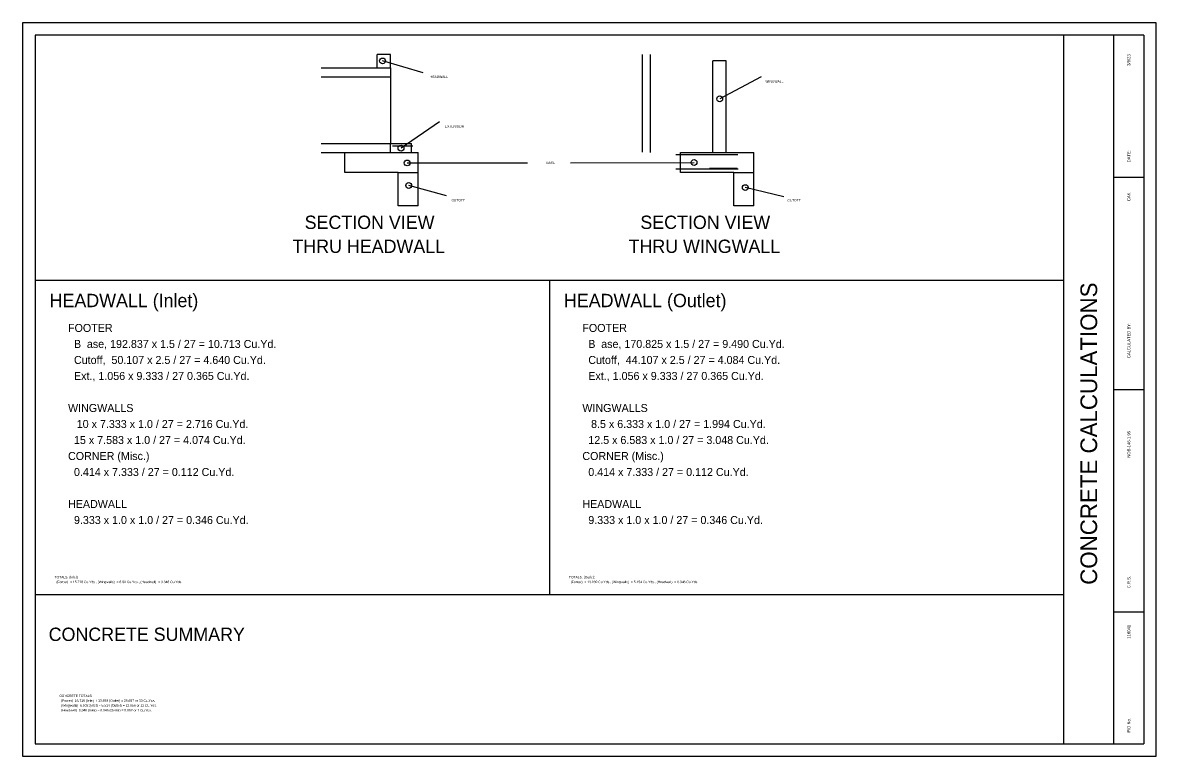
# Model space of a CAD drawing. Extents: x -1609 to 1184, y -412 to 394.
# Drawn here: x 1044.59 to 1078.59, y 161.83 to 183.83 of the extents above; entities that cross this region are included whole.
import ezdxf

# ---------------------------------------------------------------- set-up
doc = ezdxf.new("R2010")
doc.units = 0
for name, color, linetype in [('BD_P_Building', 7, 'Continuous'), ('DR_P_Headwall', 7, 'Continuous'), ('SH_Data', 7, 'Continuous'), ('ST_Details', 7, 'Continuous'), ('ST_Text', 7, 'Continuous')]:
    doc.layers.add(name, color=color, linetype=linetype)

msp = doc.modelspace()

# ---------------------------------------------------------------- linework, layer by layer
at = {"layer": 'DR_P_Headwall'}
for p, q in [((1055.22, 182.475), (1055.22, 182.875)), ((1055.62, 182.875), (1055.22, 182.875)), ((1055.62, 182.475), (1055.62, 182.875)), ((1065.688, 182.685), (1065.288, 182.685)), ((1065.288, 179.941), (1065.288, 182.685)), ((1065.688, 179.941), (1065.688, 182.685)), ((1055.62, 180.208), (1056.253, 180.208)), ((1055.62, 179.941), (1055.62, 180.208)), ((1056.253, 179.941), (1056.253, 180.208)), ((1054.253, 179.941), (1055.62, 179.941)), ((1054.253, 179.341), (1054.253, 179.941)), ((1056.253, 179.941), (1056.453, 179.941)), ((1056.453, 178.341), (1056.453, 179.941)), ((1064.321, 179.941), (1065.288, 179.941)), ((1064.321, 179.341), (1064.321, 179.941)), ((1065.688, 179.941), (1066.521, 179.941)), ((1066.521, 178.341), (1066.521, 179.941)), ((1055.853, 179.341), (1054.253, 179.341)), ((1055.853, 178.341), (1055.853, 179.341)), ((1065.921, 179.341), (1064.321, 179.341)), ((1065.921, 178.341), (1065.921, 179.341)), ((1056.453, 178.341), (1055.853, 178.341)), ((1066.521, 178.341), (1065.921, 178.341))]:
    msp.add_line(p, q, dxfattribs=at)
at = {"layer": 'SH_Data'}
for p, q in [((1056.599, 182.332), (1055.385, 182.686)), ((1066.74, 182.209), (1065.496, 181.548)), ((1057.09, 180.856), (1055.938, 180.072)), ((1056.122, 179.626), (1059.733, 179.633)), ((1061.024, 179.635), (1064.727, 179.642)), ((1057.305, 178.642), (1056.168, 178.95)), ((1067.416, 178.611), (1066.264, 178.888))]:
    msp.add_line(p, q, dxfattribs=at)
for centre in [(1055.385, 182.686), (1065.496, 181.548), (1055.938, 180.072), (1056.122, 179.626), (1064.727, 179.642), (1056.168, 178.95), (1066.264, 178.888)]:
    msp.add_circle(centre, 0.087, dxfattribs=at)
at = {"layer": 'ST_Details'}
for p, q in [((1044.591, 183.833), (1044.591, 161.833)), ((1078.591, 183.833), (1044.591, 183.833)), ((1078.591, 161.833), (1078.591, 183.833)), ((1044.966, 183.458), (1044.966, 162.208)), ((1078.216, 183.458), (1044.966, 183.458)), ((1075.816, 162.208), (1075.816, 183.458)), ((1077.316, 162.208), (1077.316, 183.458)), ((1078.216, 183.458), (1078.216, 162.208)), ((1063.176, 179.95), (1063.176, 182.875)), ((1063.421, 179.941), (1063.421, 182.875)), ((1053.547, 182.475), (1055.62, 182.475)), ((1055.62, 182.475), (1055.62, 182.473)), ((1055.62, 182.475), (1055.62, 182.208)), ((1053.547, 182.208), (1055.62, 182.208)), ((1055.62, 182.208), (1055.62, 180.208)), ((1053.547, 180.208), (1055.62, 180.208)), ((1055.62, 179.941), (1055.62, 180.208)), ((1053.547, 179.941), (1055.62, 179.941)), ((1055.62, 179.941), (1056.453, 179.941)), ((1055.687, 180.141), (1056.294, 180.141)), ((1066.043, 179.87), (1064.177, 179.87)), ((1065.288, 179.941), (1065.688, 179.941)), ((1055.853, 179.341), (1056.453, 179.341)), ((1066.049, 179.44), (1064.182, 179.44)), ((1065.187, 179.475), (1066.021, 179.475)), ((1065.921, 179.341), (1066.521, 179.341)), ((1077.316, 179.205), (1078.216, 179.205)), ((1044.966, 176.113), (1075.816, 176.113)), ((1060.391, 176.113), (1060.391, 166.681)), ((1077.316, 172.833), (1078.216, 172.833)), ((1044.966, 166.681), (1075.816, 166.681)), ((1077.316, 166.166), (1078.216, 166.166)), ((1044.966, 162.208), (1078.216, 162.208)), ((1044.591, 161.833), (1078.591, 161.833))]:
    msp.add_line(p, q, dxfattribs=at)
msp.add_lwpolyline([(1066.021, 179.87), (1065.221, 179.87)], dxfattribs=at)

# ---------------------------------------------------------------- texts
at = {"layer": 'BD_P_Building'}
for s, p in [('HEADWALL', (1056.805, 182.175)), ('WINGWALL', (1066.866, 182.036)), ('EXTENSION', (1057.254, 180.687)), ('BASE', (1060.297, 179.598)), ('CUTOFF', (1057.455, 178.473)), ('CUTOFF', (1067.523, 178.473)), ('TOTALS, (Inlet)', (1045.549, 167.17)), ('  (Footer)  = 15.718 Cu.Yds., (Wingwalls)  = 6.90 Cu.Yds., (Headwall)  = 0.346 Cu.Yds.', (1045.549, 167.026)), ('TOTALS, (Outlet)', (1060.974, 167.17)), ('  (Footer)  = 13.939 Cu.Yds., (Wingwalls)  = 5.154 Cu.Yds., (Headwall)  = 0.346 Cu.Yds.', (1060.974, 167.026)), ('CONCRETE TOTALS', (1045.689, 163.611)), ('  (Footer)  15.718 (Inlet) + 13.939 (Outlet) = 29.657 or 30 Cu.Yds.', (1045.689, 163.467)), ('  (Wingwalls)  6.902 (Inlet) + 5.514 (Outlet) = 12.056 or 12 Cu.Yds.', (1045.689, 163.323)), ('  (Headwall)  0.346 (Inlet) + 0.346 (Outlet) = 0.692 or 1 Cu.Yds.', (1045.689, 163.179))]:
    msp.add_text(s, height=0.072, dxfattribs=at).set_placement(p)
at = {"layer": 'SH_Data'}
for s, p in [('FOOTER', (1045.952, 174.559)), ('FOOTER', (1061.377, 174.559)), ('  B', (1045.952, 174.079)), ('ase, 192.837 x 1.5 / 27 = 10.713 Cu.Yd.', (1046.517, 174.079)), ('  B', (1061.377, 174.079)), ('ase, 170.825 x 1.5 / 27 = 9.490 Cu.Yd.', (1061.942, 174.079)), ('  Cutoff,  50.107 x 2.5 / 27 = 4.640 Cu.Yd.', (1045.952, 173.599)), ('  Cutoff,  44.107 x 2.5 / 27 = 4.084 Cu.Yd.', (1061.377, 173.599)), ('  Ext., 1.056 x 9.333 / 27 0.365 Cu.Yd.', (1045.952, 173.119)), ('  Ext., 1.056 x 9.333 / 27 0.365 Cu.Yd.', (1061.377, 173.119)), ('WINGWALLS', (1045.952, 172.159)), ('WINGWALLS', (1061.377, 172.159)), (' 10 x 7.333 x 1.0 / 27 = 2.716 Cu.Yd.', (1046.124, 171.679)), (' 8.5 x 6.333 x 1.0 / 27 = 1.994 Cu.Yd.', (1061.549, 171.679)), ('  15 x 7.583 x 1.0 / 27 = 4.074 Cu.Yd.', (1045.952, 171.199)), ('  12.5 x 6.583 x 1.0 / 27 = 3.048 Cu.Yd.', (1061.377, 171.199)), ('CORNER (Misc.)', (1045.952, 170.719)), ('CORNER (Misc.)', (1061.377, 170.719)), ('  0.414 x 7.333 / 27 = 0.112 Cu.Yd.', (1045.952, 170.239)), ('  0.414 x 7.333 / 27 = 0.112 Cu.Yd.', (1061.377, 170.239)), ('HEADWALL', (1045.952, 169.279)), ('HEADWALL', (1061.377, 169.279)), ('  9.333 x 1.0 x 1.0 / 27 = 0.346 Cu.Yd.', (1045.952, 168.799)), ('  9.333 x 1.0 x 1.0 / 27 = 0.346 Cu.Yd.', (1061.377, 168.799))]:
    msp.add_text(s, height=0.24, dxfattribs=at).set_placement(p)
at = {"layer": 'ST_Details'}
for s, p in [('3/8/23', (1077.811, 182.54)), ('DATE:', (1077.811, 179.645)), ('CAK', (1077.811, 178.483)), ('CALCULATED BY:', (1077.811, 173.776)), ('NOB-146-1.95', (1077.811, 170.789)), ('C.R.S.', (1077.811, 166.872)), ('116041', (1077.811, 165.359)), ('PID No.', (1077.811, 162.546))]:
    msp.add_text(s, height=0.09, rotation=90, dxfattribs=at).set_placement(p)
at = {"layer": 'ST_Text'}
for s, p in [('SECTION VIEW', (1053.049, 177.647)), ('SECTION VIEW', (1063.117, 177.647)), ('THRU HEADWALL', (1052.682, 176.927)), ('THRU WINGWALL', (1062.763, 176.927)), ('HEADWALL (Inlet)', (1045.4, 175.302)), ('HEADWALL (Outlet)', (1060.825, 175.302)), ('CONCRETE SUMMARY', (1045.371, 165.292))]:
    msp.add_text(s, height=0.4, dxfattribs=at).set_placement(p)
msp.add_text('CONCRETE CALCULATIONS', height=0.5, rotation=90, dxfattribs=at).set_placement((1076.816, 166.977))

doc.saveas('drawing.dxf')
